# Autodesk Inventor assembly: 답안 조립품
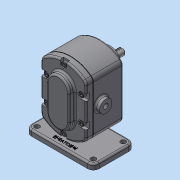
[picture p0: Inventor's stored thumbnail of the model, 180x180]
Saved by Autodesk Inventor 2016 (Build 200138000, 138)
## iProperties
Created: 2019-03
Part Number: 답안 조립품
Document SubType Name: Assembly
Designer: MIRAE
Author: MIRAE
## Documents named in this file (11)
- C:\Users\MIRAE\Desktop\490307V1017\답안 조립품.iam
- C:\Users\MIRAE\Desktop\490307V1017\본체.ipt
- C:\Users\MIRAE\Desktop\490307V1017\커버.ipt
- C:\Users\MIRAE\Desktop\490307V1017\메인축.ipt
- C:\Users\MIRAE\Desktop\490307V1017\키 6 x 6 x 18.ipt
- C:\Users\MIRAE\Desktop\490307V1017\베어링부시.ipt
- C:\Users\MIRAE\Desktop\490307V1017\개스킷.ipt
- C:\Users\MIRAE\Desktop\490307V1017\서브축.ipt
- C:\Users\MIRAE\Desktop\490307V1017\오일 실 16 28 7.ipt
- C:\Users\MIRAE\Desktop\490307V1017\볼트 M5.ipt
- C:\Users\MIRAE\Desktop\490307V1017\스퍼기어.ipt
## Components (1 placed, 1 different names)
1. 개스킷:1
